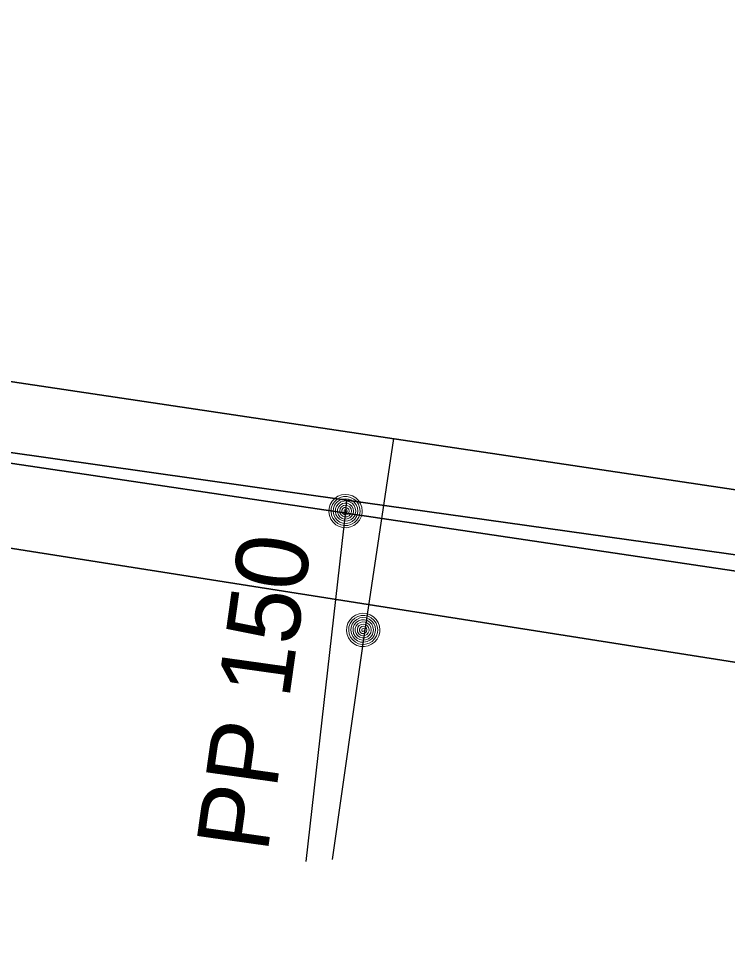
# Model space of a CAD drawing. Extents: x -866761 to -866592, y -1013996 to -1013877.
# Drawn here: x -866702.42 to -866692.58, y -1013971.12 to -1013958.25 of the extents above; entities that cross this region are included whole.
import ezdxf

# ---------------------------------------------------------------- set-up
doc = ezdxf.new("R2010")
doc.units = 0
doc.header["$LTSCALE"] = 0.44
for name, color, linetype, lineweight in [('1', 7, 'Continuous', 35), ('12', 7, 'Continuous', 13), ('21', 7, 'Continuous', 35), ('23', 7, 'Continuous', 25), ('3', 7, 'Continuous', 25), ('32', 7, 'Continuous', 13)]:
    doc.layers.add(name, color=color, linetype=linetype, lineweight=lineweight)

msp = doc.modelspace()

# ---------------------------------------------------------------- linework, layer by layer
at = {"layer": '1'}
msp.add_line((-866612.967, -1013977.763), (-866734.931, -1013959.586), dxfattribs=at)
for points in [[(-866612.815, -1013977.108), (-866621.035, -1013976.325), (-866621.378, -1013976.297), (-866626.243, -1013975.519), (-866632.94, -1013974.51), (-866645.03, -1013972.86), (-866647.305, -1013972.501), (-866654.48, -1013971.31), (-866668.882, -1013969.171), (-866678.229, -1013967.78), (-866685.446, -1013966.718), (-866689.8, -1013966.06), (-866697.865, -1013964.927), (-866723.097, -1013961.352), (-866726.923, -1013960.77), (-866727.214, -1013960.734), (-866737.38, -1013959.64), (-866746.09, -1013958.48), (-866747.84, -1013958.25), (-866748.13, -1013958.99), (-866750.15, -1013958.69)], [(-866613.338, -1013979.363), (-866624.951, -1013977.802), (-866715.256, -1013963.593), (-866735.102, -1013960.577)]]:
    msp.add_lwpolyline(points, dxfattribs=at)
at = {"layer": '12'}
for points in [[(-866697.649, -1013965.08), (-866697.655, -1013965.028), (-866697.672, -1013964.978), (-866697.701, -1013964.934), (-866697.738, -1013964.897), (-866697.783, -1013964.87), (-866697.833, -1013964.853), (-866697.886, -1013964.849), (-866697.938, -1013964.856), (-866697.987, -1013964.875), (-866698.03, -1013964.904), (-866698.066, -1013964.943), (-866698.092, -1013964.988), (-866698.108, -1013965.039), (-866698.111, -1013965.091), (-866698.103, -1013965.143), (-866698.083, -1013965.192), (-866698.052, -1013965.235), (-866698.013, -1013965.269), (-866697.967, -1013965.295), (-866697.916, -1013965.309), (-866697.863, -1013965.311), (-866697.812, -1013965.301), (-866697.764, -1013965.28), (-866697.721, -1013965.249), (-866697.687, -1013965.208), (-866697.663, -1013965.162), (-866697.651, -1013965.111)], [(-866697.679, -1013965.08), (-866697.685, -1013965.031), (-866697.702, -1013964.985), (-866697.73, -1013964.945), (-866697.767, -1013964.913), (-866697.811, -1013964.891), (-866697.859, -1013964.88), (-866697.908, -1013964.88), (-866697.955, -1013964.893), (-866697.998, -1013964.917), (-866698.034, -1013964.95), (-866698.061, -1013964.991), (-866698.077, -1013965.038), (-866698.081, -1013965.087), (-866698.074, -1013965.135), (-866698.055, -1013965.18), (-866698.025, -1013965.22), (-866697.987, -1013965.251), (-866697.943, -1013965.271), (-866697.895, -1013965.281), (-866697.846, -1013965.279), (-866697.799, -1013965.264), (-866697.756, -1013965.239), (-866697.722, -1013965.205), (-866697.696, -1013965.163), (-866697.682, -1013965.116)], [(-866697.709, -1013965.08), (-866697.715, -1013965.035), (-866697.732, -1013964.993), (-866697.76, -1013964.958), (-866697.796, -1013964.931), (-866697.838, -1013964.914), (-866697.883, -1013964.909), (-866697.928, -1013964.915), (-866697.969, -1013964.934), (-866698.004, -1013964.962), (-866698.031, -1013964.999), (-866698.047, -1013965.041), (-866698.051, -1013965.086), (-866698.044, -1013965.131), (-866698.025, -1013965.172), (-866697.996, -1013965.206), (-866697.959, -1013965.232), (-866697.916, -1013965.248), (-866697.871, -1013965.251), (-866697.826, -1013965.243), (-866697.786, -1013965.223), (-866697.752, -1013965.194), (-866697.726, -1013965.156), (-866697.712, -1013965.113)], [(-866697.739, -1013965.08), (-866697.744, -1013965.039), (-866697.762, -1013965.002), (-866697.789, -1013964.971), (-866697.824, -1013964.95), (-866697.864, -1013964.939), (-866697.905, -1013964.941), (-866697.944, -1013964.954), (-866697.978, -1013964.978), (-866698.003, -1013965.01), (-866698.018, -1013965.048), (-866698.021, -1013965.089), (-866698.013, -1013965.129), (-866697.993, -1013965.165), (-866697.964, -1013965.194), (-866697.927, -1013965.213), (-866697.887, -1013965.221), (-866697.846, -1013965.217), (-866697.808, -1013965.202), (-866697.776, -1013965.176), (-866697.753, -1013965.142), (-866697.74, -1013965.103)], [(-866697.769, -1013965.08), (-866697.774, -1013965.044), (-866697.792, -1013965.012), (-866697.818, -1013964.987), (-866697.852, -1013964.972), (-866697.888, -1013964.969), (-866697.923, -1013964.977), (-866697.954, -1013964.997), (-866697.977, -1013965.025), (-866697.99, -1013965.059), (-866697.99, -1013965.096), (-866697.979, -1013965.131), (-866697.958, -1013965.16), (-866697.928, -1013965.181), (-866697.893, -1013965.191), (-866697.856, -1013965.189), (-866697.822, -1013965.175), (-866697.795, -1013965.152), (-866697.776, -1013965.12), (-866697.769, -1013965.085)], [(-866697.799, -1013965.08), (-866697.804, -1013965.049), (-866697.821, -1013965.023), (-866697.847, -1013965.006), (-866697.877, -1013964.999), (-866697.908, -1013965.003), (-866697.935, -1013965.02), (-866697.953, -1013965.044), (-866697.961, -1013965.075), (-866697.957, -1013965.105), (-866697.942, -1013965.133), (-866697.918, -1013965.152), (-866697.888, -1013965.161), (-866697.857, -1013965.158), (-866697.829, -1013965.144), (-866697.809, -1013965.12), (-866697.799, -1013965.091)], [(-866697.829, -1013965.08), (-866697.834, -1013965.056), (-866697.851, -1013965.038), (-866697.874, -1013965.029), (-866697.898, -1013965.032), (-866697.919, -1013965.046), (-866697.93, -1013965.068), (-866697.93, -1013965.093), (-866697.918, -1013965.114), (-866697.898, -1013965.128), (-866697.873, -1013965.131), (-866697.85, -1013965.122), (-866697.834, -1013965.104)], [(-866697.859, -1013965.08), (-866697.864, -1013965.065), (-866697.879, -1013965.059), (-866697.894, -1013965.063), (-866697.901, -1013965.077), (-866697.897, -1013965.092), (-866697.884, -1013965.101), (-866697.869, -1013965.098), (-866697.859, -1013965.086)]]:
    msp.add_lwpolyline(points, close=True, dxfattribs=at)
at = {"layer": '21'}
msp.add_line((-866709.04, -1013962.31), (-866647.459, -1013971.5), dxfattribs=at)
at = {"layer": '23'}
msp.add_lwpolyline([(-866697.214, -1013964.075), (-866697.62, -1013966.79), (-866698.066, -1013969.91)], dxfattribs=at)
at = {"layer": '3'}
msp.add_lwpolyline([(-866697.865, -1013964.927), (-866697.88, -1013965.08), (-866698.43, -1013969.94)], dxfattribs=at)
at = {"layer": '32'}
for points in [[(-866697.404, -1013966.728), (-866697.41, -1013966.676), (-866697.427, -1013966.626), (-866697.456, -1013966.582), (-866697.493, -1013966.545), (-866697.538, -1013966.518), (-866697.588, -1013966.501), (-866697.641, -1013966.497), (-866697.693, -1013966.504), (-866697.742, -1013966.523), (-866697.785, -1013966.552), (-866697.821, -1013966.591), (-866697.847, -1013966.636), (-866697.863, -1013966.687), (-866697.866, -1013966.739), (-866697.858, -1013966.791), (-866697.838, -1013966.84), (-866697.807, -1013966.883), (-866697.768, -1013966.917), (-866697.722, -1013966.943), (-866697.671, -1013966.957), (-866697.618, -1013966.959), (-866697.567, -1013966.949), (-866697.519, -1013966.928), (-866697.476, -1013966.897), (-866697.442, -1013966.856), (-866697.418, -1013966.81), (-866697.406, -1013966.759)], [(-866697.434, -1013966.728), (-866697.44, -1013966.679), (-866697.457, -1013966.633), (-866697.485, -1013966.593), (-866697.522, -1013966.561), (-866697.566, -1013966.539), (-866697.614, -1013966.528), (-866697.663, -1013966.528), (-866697.71, -1013966.541), (-866697.753, -1013966.565), (-866697.789, -1013966.598), (-866697.816, -1013966.639), (-866697.832, -1013966.686), (-866697.836, -1013966.735), (-866697.829, -1013966.783), (-866697.81, -1013966.828), (-866697.78, -1013966.868), (-866697.742, -1013966.899), (-866697.698, -1013966.919), (-866697.65, -1013966.929), (-866697.601, -1013966.927), (-866697.554, -1013966.912), (-866697.511, -1013966.887), (-866697.477, -1013966.853), (-866697.451, -1013966.811), (-866697.437, -1013966.764)], [(-866697.464, -1013966.728), (-866697.47, -1013966.683), (-866697.487, -1013966.641), (-866697.515, -1013966.606), (-866697.551, -1013966.579), (-866697.593, -1013966.562), (-866697.638, -1013966.557), (-866697.683, -1013966.563), (-866697.724, -1013966.582), (-866697.759, -1013966.61), (-866697.786, -1013966.647), (-866697.802, -1013966.689), (-866697.806, -1013966.734), (-866697.799, -1013966.779), (-866697.78, -1013966.82), (-866697.751, -1013966.854), (-866697.714, -1013966.88), (-866697.671, -1013966.896), (-866697.626, -1013966.899), (-866697.581, -1013966.891), (-866697.541, -1013966.871), (-866697.507, -1013966.842), (-866697.481, -1013966.804), (-866697.467, -1013966.761)], [(-866697.494, -1013966.728), (-866697.499, -1013966.687), (-866697.517, -1013966.65), (-866697.544, -1013966.619), (-866697.579, -1013966.598), (-866697.619, -1013966.587), (-866697.66, -1013966.589), (-866697.699, -1013966.602), (-866697.733, -1013966.626), (-866697.758, -1013966.658), (-866697.773, -1013966.696), (-866697.776, -1013966.737), (-866697.768, -1013966.777), (-866697.748, -1013966.813), (-866697.719, -1013966.842), (-866697.682, -1013966.861), (-866697.642, -1013966.869), (-866697.601, -1013966.865), (-866697.563, -1013966.85), (-866697.531, -1013966.824), (-866697.508, -1013966.79), (-866697.495, -1013966.751)], [(-866697.524, -1013966.728), (-866697.529, -1013966.692), (-866697.547, -1013966.66), (-866697.573, -1013966.635), (-866697.607, -1013966.62), (-866697.643, -1013966.617), (-866697.678, -1013966.625), (-866697.709, -1013966.645), (-866697.732, -1013966.673), (-866697.745, -1013966.707), (-866697.745, -1013966.744), (-866697.734, -1013966.779), (-866697.713, -1013966.808), (-866697.683, -1013966.829), (-866697.648, -1013966.839), (-866697.611, -1013966.837), (-866697.577, -1013966.823), (-866697.55, -1013966.8), (-866697.531, -1013966.768), (-866697.524, -1013966.733)], [(-866697.554, -1013966.728), (-866697.559, -1013966.697), (-866697.576, -1013966.671), (-866697.602, -1013966.654), (-866697.632, -1013966.647), (-866697.663, -1013966.651), (-866697.69, -1013966.668), (-866697.708, -1013966.692), (-866697.716, -1013966.723), (-866697.712, -1013966.753), (-866697.697, -1013966.781), (-866697.673, -1013966.8), (-866697.643, -1013966.809), (-866697.612, -1013966.806), (-866697.584, -1013966.792), (-866697.564, -1013966.768), (-866697.554, -1013966.739)], [(-866697.584, -1013966.728), (-866697.589, -1013966.704), (-866697.606, -1013966.686), (-866697.629, -1013966.677), (-866697.653, -1013966.68), (-866697.674, -1013966.694), (-866697.685, -1013966.716), (-866697.685, -1013966.741), (-866697.673, -1013966.762), (-866697.653, -1013966.776), (-866697.628, -1013966.779), (-866697.605, -1013966.77), (-866697.589, -1013966.752)], [(-866697.614, -1013966.728), (-866697.619, -1013966.713), (-866697.634, -1013966.707), (-866697.649, -1013966.711), (-866697.656, -1013966.725), (-866697.652, -1013966.74), (-866697.639, -1013966.749), (-866697.624, -1013966.746), (-866697.614, -1013966.734)]]:
    msp.add_lwpolyline(points, close=True, dxfattribs=at)

# ---------------------------------------------------------------- texts
at = {"layer": '23'}
msp.add_text('PP 150', height=1, rotation=82, dxfattribs=at).set_placement((-866698.963, -1013969.833))

doc.saveas('drawing.dxf')
